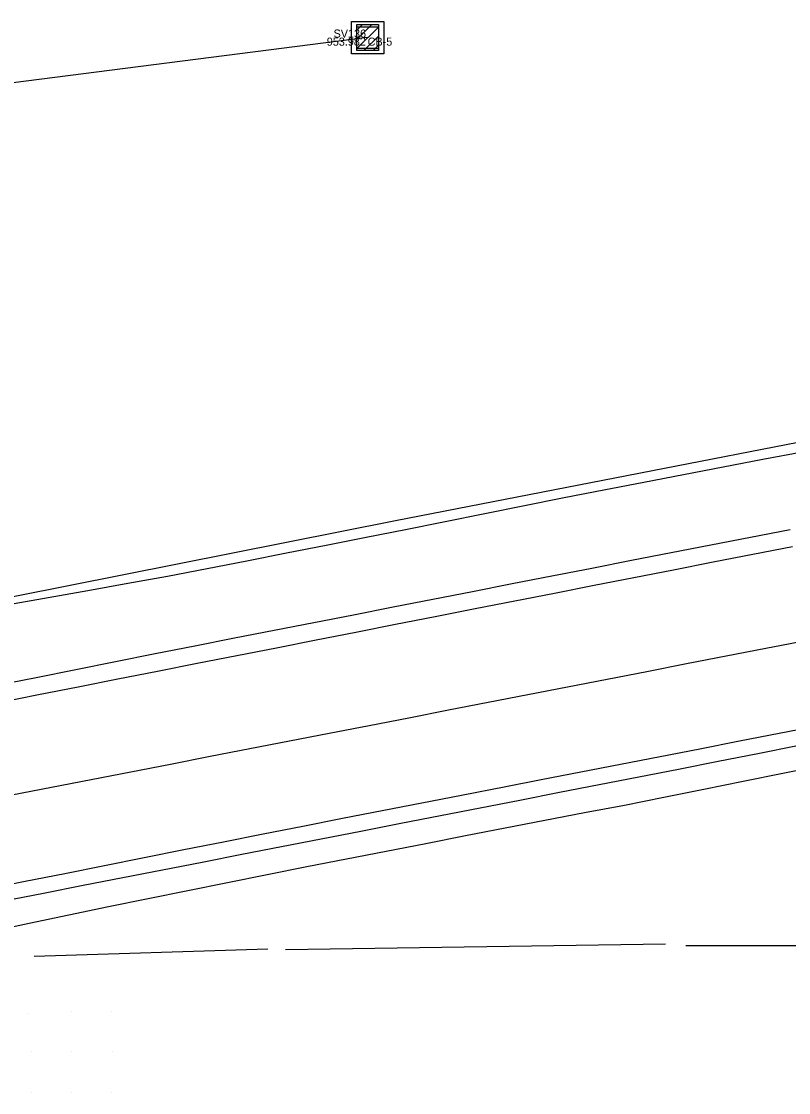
# Model space of a CAD drawing. Extents: x 2262025 to 2264532, y 740981 to 742724.
# Drawn here: x 2263355.9 to 2263450.8, y 742163.2 to 742295.6 of the extents above; entities that cross this region are included whole.
import ezdxf

# ---------------------------------------------------------------- set-up
doc = ezdxf.new("R2010")
doc.units = 0
for name, color, linetype in [('GE_X_Alignment_1000_Curve_Data', 7, 'Continuous'), ('GE_X_Alignment_100_Bearings', 7, 'Continuous'), ('GE_X_Alignment_100_Cardinal_Points', 7, 'Continuous'), ('GE_X_Alignment_100_Curve_Data', 7, 'Continuous'), ('Ground Shots', 7, 'Continuous'), ('HY_X_Spring_Cells', 7, 'Continuous'), ('RW_X_CL', 7, 'Continuous'), ('RW_X_CL_1000_Distances', 7, 'Continuous'), ('RW_X_CL_100_Curve_Data', 7, 'Continuous'), ('RW_X_CL_100_Stations', 7, 'Continuous'), ('RW_X_CL_500_Stations', 7, 'Continuous'), ('SC_Scratch2', 7, 'Continuous'), ('SV_X_Text_Comment', 7, 'Continuous')]:
    doc.layers.add(name, color=color, linetype=linetype)

msp = doc.modelspace()

# ---------------------------------------------------------------- linework, layer by layer
at = {"layer": 'GE_X_Alignment_1000_Curve_Data'}
for points in [[(2263450.96, 742232.75), (2263446.05, 742231.79), (2263441.14, 742230.83), (2263436.24, 742229.87), (2263431.33, 742228.92), (2263426.42, 742227.96), (2263421.51, 742227), (2263416.61, 742226.04), (2263411.7, 742225.08), (2263406.79, 742224.12), (2263401.89, 742223.16), (2263396.98, 742222.2), (2263392.07, 742221.25), (2263387.16, 742220.29), (2263382.26, 742219.33), (2263377.35, 742218.35), (2263372.45, 742217.38), (2263367.55, 742216.4), (2263362.64, 742215.42), (2263357.74, 742214.44), (2263352.84, 742213.47)], [(2263353.74, 742186.87), (2263358.64, 742187.83), (2263363.55, 742188.79), (2263368.46, 742189.75), (2263373.36, 742190.7), (2263378.27, 742191.66), (2263383.18, 742192.62), (2263388.09, 742193.58), (2263392.99, 742194.54), (2263397.9, 742195.49), (2263402.81, 742196.45), (2263407.72, 742197.41), (2263412.62, 742198.37), (2263417.53, 742199.33), (2263422.44, 742200.28), (2263427.35, 742201.24), (2263432.25, 742202.2), (2263437.16, 742203.16), (2263442.07, 742204.13), (2263446.97, 742205.09), (2263451.88, 742206.05)]]:
    msp.add_lwpolyline(points, dxfattribs=at)
at = {"layer": 'GE_X_Alignment_100_Bearings'}
for p, q in [((2263388.55, 742180.86), (2263435.55, 742181.53)), ((2263438.05, 742181.33), (2263462.02, 742181.33)), ((2263357.49, 742180.04), (2263386.39, 742180.92))]:
    msp.add_line(p, q, dxfattribs=at)
at = {"layer": 'GE_X_Alignment_100_Cardinal_Points'}
msp.add_lwpolyline([(2263328.11, 742219.18), (2263402.15, 742233.89), (2263485.21, 742250.04), (2263528.29, 742258.28), (2263557.73, 742264.97), (2263579.88, 742270.58), (2263590.62, 742273.55), (2263602.77, 742276.39), (2263620.53, 742279.84), (2263656.59, 742286.79), (2263668.47, 742288.55)], dxfattribs=at)
at = {"layer": 'GE_X_Alignment_100_Curve_Data'}
for points in [[(2263354.3, 742223.48), (2263359.22, 742224.36), (2263364.14, 742225.24), (2263369.06, 742226.12), (2263373.98, 742227), (2263378.9, 742227.94), (2263383.8, 742228.9), (2263388.71, 742229.87), (2263393.61, 742230.84), (2263398.52, 742231.81), (2263403.42, 742232.78), (2263408.32, 742233.76), (2263413.23, 742234.75), (2263418.13, 742235.73), (2263423.03, 742236.71), (2263427.94, 742237.66), (2263432.85, 742238.61), (2263437.76, 742239.56), (2263442.67, 742240.51), (2263447.58, 742241.46), (2263452.49, 742242.39)], [(2263454.97, 742203.58), (2263450.07, 742202.59), (2263445.17, 742201.6), (2263440.27, 742200.61), (2263435.36, 742199.64), (2263430.46, 742198.67), (2263425.55, 742197.73), (2263420.64, 742196.78), (2263415.73, 742195.84), (2263410.82, 742194.89), (2263405.91, 742193.93), (2263401, 742192.98), (2263396.09, 742192.02), (2263391.19, 742191.06), (2263386.28, 742190.08), (2263381.38, 742189.09), (2263376.48, 742188.1), (2263371.58, 742187.12), (2263366.68, 742186.11), (2263361.79, 742185.1), (2263356.89, 742184.07), (2263352, 742183.03)]]:
    msp.add_lwpolyline(points, dxfattribs=at)
at = {"layer": 'Ground Shots'}
for p, q in [((2263362.14, 742173.13), (2263362.14, 742173.13)), ((2263367.05, 742173.14), (2263367.05, 742173.14)), ((2263356.84, 742172.92), (2263356.84, 742172.92)), ((2263357.14, 742168.3), (2263357.14, 742168.3)), ((2263362.16, 742168.19), (2263362.16, 742168.19)), ((2263367.15, 742168.23), (2263367.15, 742168.23)), ((2263357.14, 742163.23), (2263357.14, 742163.23)), ((2263362.09, 742163.16), (2263362.09, 742163.16)), ((2263367.05, 742163.18), (2263367.05, 742163.18))]:
    msp.add_line(p, q, dxfattribs=at)
at = {"layer": 'RW_X_CL_1000_Distances'}
for points in [[(2263353.13, 742211.4), (2263358.03, 742212.37), (2263362.94, 742213.33), (2263367.84, 742214.3), (2263372.75, 742215.26), (2263377.65, 742216.23), (2263382.56, 742217.2), (2263387.47, 742218.16), (2263392.37, 742219.13), (2263397.28, 742220.09), (2263402.18, 742221.06), (2263407.09, 742222.02), (2263412, 742222.99), (2263416.9, 742223.95), (2263421.81, 742224.91), (2263426.72, 742225.87), (2263431.62, 742226.83), (2263436.53, 742227.8), (2263441.44, 742228.76), (2263446.34, 742229.72), (2263451.25, 742230.68)], [(2263454.52, 742208.5), (2263449.61, 742207.55), (2263444.7, 742206.59), (2263439.79, 742205.63), (2263434.88, 742204.68), (2263429.98, 742203.72), (2263425.07, 742202.77), (2263420.16, 742201.81), (2263415.8, 742200.96), (2263410.34, 742199.9), (2263405.44, 742198.95), (2263400.53, 742197.99), (2263395.62, 742197.04), (2263390.71, 742196.07), (2263385.81, 742195.1), (2263380.91, 742194.12), (2263376, 742193.15), (2263371.1, 742192.17), (2263366.19, 742191.2), (2263361.29, 742190.22), (2263356.39, 742189.25), (2263351.48, 742188.27)]]:
    msp.add_lwpolyline(points, dxfattribs=at)
at = {"layer": 'RW_X_CL_100_Curve_Data'}
for p, q in [((2263397.39, 742293.36), (2263399.23, 742295.2)), ((2263397.39, 742294.49), (2263398.1, 742295.2)), ((2263397.39, 742293.36), (2263399.23, 742295.2)), ((2263397.39, 742294.49), (2263398.1, 742295.2)), ((2263397.39, 742292.23), (2263400.06, 742294.89)), ((2263397.39, 742292.23), (2263400.06, 742294.89)), ((2263398.26, 742291.97), (2263400.06, 742293.76)), ((2263398.26, 742291.97), (2263400.06, 742293.76)), ((2263399.39, 742291.97), (2263400.06, 742292.63)), ((2263399.39, 742291.97), (2263400.06, 742292.63))]:
    msp.add_line(p, q, dxfattribs=at)
for points in [[(2263396.72, 742295.58), (2263400.72, 742295.58), (2263400.72, 742291.58), (2263396.72, 742291.58)], [(2263396.72, 742295.58), (2263400.72, 742295.58), (2263400.72, 742291.58), (2263396.72, 742291.58)], [(2263397.39, 742295.2), (2263400.06, 742295.2), (2263400.06, 742291.97), (2263397.39, 742291.97)], [(2263397.39, 742295.2), (2263400.06, 742295.2), (2263400.06, 742291.97), (2263397.39, 742291.97)], [(2263397.39, 742294.91), (2263400.06, 742294.91), (2263400.06, 742292.25), (2263397.39, 742292.25)], [(2263397.39, 742294.91), (2263400.06, 742294.91), (2263400.06, 742292.25), (2263397.39, 742292.25)]]:
    msp.add_lwpolyline(points, close=True, dxfattribs=at)
at = {"layer": 'RW_X_CL_100_Stations'}
for p, q in [((2263398.72, 742295.58), (2263398.72, 742295.58)), ((2263398.72, 742295.58), (2263398.72, 742295.58)), ((2263398.72, 742294.91), (2263398.72, 742294.91)), ((2263398.72, 742294.91), (2263398.72, 742294.91)), ((2263397.39, 742293.58), (2263397.39, 742293.58)), ((2263397.39, 742293.58), (2263397.39, 742293.58)), ((2263398.72, 742293.58), (2263398.72, 742293.58)), ((2263398.72, 742293.58), (2263398.72, 742293.58)), ((2263398.72, 742293.58), (2263398.72, 742293.58)), ((2263398.72, 742293.58), (2263398.72, 742293.58)), ((2263400.06, 742293.58), (2263400.06, 742293.58)), ((2263400.06, 742293.58), (2263400.06, 742293.58)), ((2263398.72, 742292.25), (2263398.72, 742292.25)), ((2263398.72, 742292.25), (2263398.72, 742292.25)), ((2263398.72, 742291.97), (2263398.72, 742291.97)), ((2263398.72, 742291.97), (2263398.72, 742291.97)), ((2263398.72, 742291.58), (2263398.72, 742291.58)), ((2263398.72, 742291.58), (2263398.72, 742291.58))]:
    msp.add_line(p, q, dxfattribs=at)
at = {"layer": 'RW_X_CL_500_Stations'}
msp.add_line((2263398.72, 742293.58), (2263176.67, 742265.17), dxfattribs=at)
at = {"layer": 'SC_Scratch2'}
msp.add_lwpolyline([(2263452.88, 742219.01), (2263447.97, 742218.06), (2263443.06, 742217.1), (2263438.15, 742216.15), (2263433.24, 742215.19), (2263428.34, 742214.24), (2263423.43, 742213.28), (2263418.52, 742212.33), (2263413.61, 742211.37), (2263408.7, 742210.42), (2263403.8, 742209.46), (2263398.89, 742208.51), (2263393.98, 742207.55), (2263389.07, 742206.6), (2263384.16, 742205.64), (2263379.26, 742204.69), (2263374.35, 742203.73), (2263369.44, 742202.77), (2263364.53, 742201.82), (2263359.62, 742200.86), (2263354.72, 742199.91)], dxfattribs=at)

# ---------------------------------------------------------------- texts
at = {"layer": 'HY_X_Spring_Cells'}
msp.add_text('953.982', height=1, dxfattribs=at).set_placement((2263393.67, 742292.58))
msp.add_text('953.982', height=1, dxfattribs=at).set_placement((2263393.67, 742292.58))
at = {"layer": 'RW_X_CL'}
msp.add_text('CB-5', height=1, dxfattribs=at).set_placement((2263398.72, 742292.58))
msp.add_text('CB-5', height=1, dxfattribs=at).set_placement((2263398.72, 742292.58))
at = {"layer": 'SV_X_Text_Comment'}
msp.add_text('SV136', height=1, dxfattribs=at).set_placement((2263394.51, 742293.58))
msp.add_text('SV136', height=1, dxfattribs=at).set_placement((2263394.51, 742293.58))

doc.saveas('drawing.dxf')
